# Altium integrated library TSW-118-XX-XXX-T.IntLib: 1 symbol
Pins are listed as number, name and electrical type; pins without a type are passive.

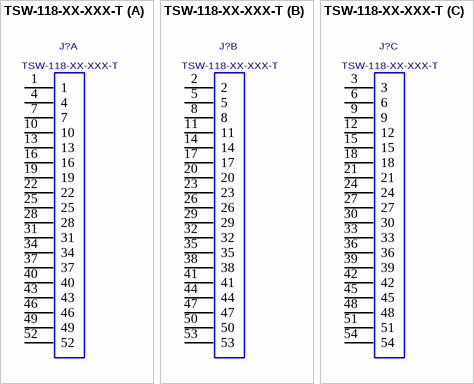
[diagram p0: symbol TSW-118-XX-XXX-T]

## TSW-118-XX-XXX-T
designator J?
.025[0.64] SQ. POST TERMINAL STRIP ASSEMBLY.; MANUFACTURER: SAMTEC
footprint TSW-118-XX-XXX-T
part A pins: 1, 4, 7, 10, 13, 16, 19, 22, 25, 28, 31, 34, 37, 40, 43, 46, 49, 52
part B pins: 2, 5, 8, 11, 14, 17, 20, 23, 26, 29, 32, 35, 38, 41, 44, 47, 50, 53
part C pins: 3, 6, 9, 12, 15, 18, 21, 24, 27, 30, 33, 36, 39, 42, 45, 48, 51, 54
